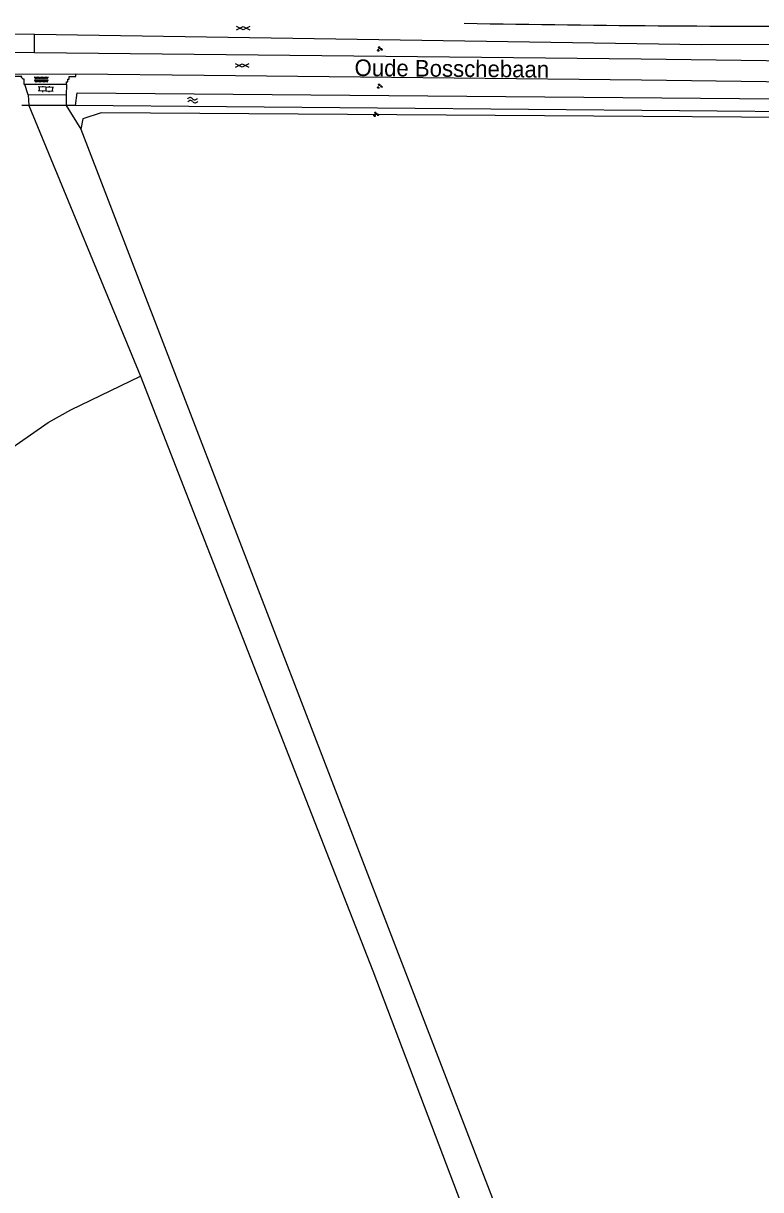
# Model space of a CAD drawing. Extents: x 134297 to 137000, y 403500 to 406000.
# Drawn here: x 136777.7 to 136889, y 405338.4 to 405514.3 of the extents above; entities that cross this region are included whole.
import ezdxf

# ---------------------------------------------------------------- set-up
doc = ezdxf.new("R2010")
doc.units = 0
for name, color, linetype in [('gg-anno-openbare ruimte label', 7, 'Continuous'), ('gg-knt-bronhoudergrens', 7, 'Continuous'), ('gg-knt-onverhard', 7, 'Continuous'), ('gg-knt-verharding', 7, 'Continuous'), ('gg-kntw-bovenkant insteek waterloop', 7, 'Continuous'), ('gt-grn-groengrens', 7, 'Continuous'), ('gt-symb-gesloten verharding', 7, 'Continuous'), ('gt-symb-groenvak', 7, 'Continuous'), ('gt-symb-klinker verharding', 7, 'Continuous'), ('gt-symb-overige verharding', 7, 'Continuous'), ('gt-symb-watersymbool', 7, 'Continuous')]:
    doc.layers.add(name, color=color, linetype=linetype)

# ---------------------------------------------------------------- blocks, each defined once
blk = doc.blocks.new('gt0-WA')
at = {"layer": 'gt-symb-watersymbool'}
for centre, start, end in [((-0.32, 0.02), 28.0725, 151.9275), ((0.43, 0.42), 208.0725, 331.9275), ((-0.32, -0.43), 28.0725, 151.9275), ((0.43, -0.03), 208.0725, 331.9275)]:
    blk.add_arc(centre, 0.425, start, end, dxfattribs=at)
blk = doc.blocks.new('gt0-GESVH1')
at = {"layer": 'gt-symb-gesloten verharding'}
for p, q in [((-0.99, -0.26), (0.01, 0.24)), ((0.01, -0.26), (-0.99, 0.24)), ((0.01, 0.24), (1.01, -0.26)), ((1.01, 0.24), (0.01, -0.26))]:
    blk.add_line(p, q, dxfattribs=at)
blk = doc.blocks.new('gt0-GRVAK')
at = {"layer": 'gt-symb-groenvak'}
for p, q in [((-0.11, 0.19), (-0.23, 0.24)), ((-0.18, 0.15), (0.09, 0.15)), ((-0.09, 0.21), (-0.16, 0.32)), ((-0.05, 0.21), (-0.05, 0.39)), ((0, 0.21), (0.06, 0.32)), ((0.01, 0.19), (0.13, 0.24)), ((0.26, -0.05), (0.2, 0.06)), ((0.3, -0.05), (0.3, 0.13)), ((0.35, -0.05), (0.41, 0.06)), ((-0.24, -0.23), (-0.36, -0.18)), ((-0.32, -0.26), (-0.05, -0.26)), ((-0.23, -0.21), (-0.29, -0.09)), ((-0.18, -0.2), (-0.18, -0.02)), ((-0.14, -0.21), (-0.07, -0.09)), ((-0.12, -0.23), (0, -0.18)), ((0.24, -0.07), (0.12, -0.02)), ((0.17, -0.11), (0.44, -0.11)), ((0.37, -0.07), (0.49, -0.02))]:
    blk.add_line(p, q, dxfattribs=at)
blk = doc.blocks.new('gt0-OVH')
at = {"layer": 'gt-symb-overige verharding'}
for points in [[(-0.97, 0.3), (-0.97, 0.31), (-0.96, 0.32), (-0.97, 0.33), (-0.97, 0.34), (-0.98, 0.35), (-0.99, 0.35), (-1, 0.36), (-1.01, 0.35), (-1.02, 0.35), (-1.03, 0.34), (-1.03, 0.33), (-1.04, 0.32), (-1.03, 0.31), (-1.03, 0.3), (-1.02, 0.29), (-1.01, 0.29), (-1, 0.28), (-0.99, 0.29), (-0.98, 0.29)], [(-0.87, 0.11), (-0.87, 0.12), (-0.86, 0.13), (-0.87, 0.14), (-0.87, 0.15), (-0.88, 0.16), (-0.89, 0.16), (-0.9, 0.16), (-0.91, 0.16), (-0.92, 0.16), (-0.93, 0.15), (-0.93, 0.14), (-0.94, 0.13), (-0.93, 0.12), (-0.93, 0.11), (-0.92, 0.1), (-0.91, 0.09), (-0.9, 0.09), (-0.89, 0.09), (-0.88, 0.1)], [(-0.77, 0.3), (-0.77, 0.31), (-0.76, 0.32), (-0.77, 0.33), (-0.77, 0.34), (-0.78, 0.35), (-0.79, 0.35), (-0.8, 0.36), (-0.81, 0.35), (-0.82, 0.35), (-0.83, 0.34), (-0.83, 0.33), (-0.84, 0.32), (-0.83, 0.31), (-0.83, 0.3), (-0.82, 0.29), (-0.81, 0.29), (-0.8, 0.28), (-0.79, 0.29), (-0.78, 0.29)], [(-0.67, 0.11), (-0.67, 0.12), (-0.66, 0.13), (-0.67, 0.14), (-0.67, 0.15), (-0.68, 0.16), (-0.69, 0.16), (-0.7, 0.16), (-0.71, 0.16), (-0.72, 0.16), (-0.73, 0.15), (-0.73, 0.14), (-0.74, 0.13), (-0.73, 0.12), (-0.73, 0.11), (-0.72, 0.1), (-0.71, 0.09), (-0.7, 0.09), (-0.69, 0.09), (-0.68, 0.1)], [(-0.57, 0.3), (-0.57, 0.31), (-0.56, 0.32), (-0.57, 0.33), (-0.57, 0.34), (-0.58, 0.35), (-0.59, 0.35), (-0.6, 0.36), (-0.61, 0.35), (-0.62, 0.35), (-0.63, 0.34), (-0.63, 0.33), (-0.64, 0.32), (-0.63, 0.31), (-0.63, 0.3), (-0.62, 0.29), (-0.61, 0.29), (-0.6, 0.28), (-0.59, 0.29), (-0.58, 0.29)], [(-0.47, 0.11), (-0.47, 0.12), (-0.46, 0.13), (-0.47, 0.14), (-0.47, 0.15), (-0.48, 0.16), (-0.49, 0.16), (-0.5, 0.16), (-0.51, 0.16), (-0.52, 0.16), (-0.53, 0.15), (-0.53, 0.14), (-0.54, 0.13), (-0.53, 0.12), (-0.53, 0.11), (-0.52, 0.1), (-0.51, 0.09), (-0.5, 0.09), (-0.49, 0.09), (-0.48, 0.1)], [(-0.37, 0.3), (-0.37, 0.31), (-0.36, 0.32), (-0.37, 0.33), (-0.37, 0.34), (-0.38, 0.35), (-0.39, 0.35), (-0.4, 0.36), (-0.41, 0.35), (-0.42, 0.35), (-0.43, 0.34), (-0.43, 0.33), (-0.44, 0.32), (-0.43, 0.31), (-0.43, 0.3), (-0.42, 0.29), (-0.41, 0.29), (-0.4, 0.28), (-0.39, 0.29), (-0.38, 0.29)], [(-0.27, 0.11), (-0.27, 0.12), (-0.26, 0.13), (-0.27, 0.14), (-0.27, 0.15), (-0.28, 0.16), (-0.29, 0.16), (-0.3, 0.16), (-0.31, 0.16), (-0.32, 0.16), (-0.33, 0.15), (-0.33, 0.14), (-0.34, 0.13), (-0.33, 0.12), (-0.33, 0.11), (-0.32, 0.1), (-0.31, 0.09), (-0.3, 0.09), (-0.29, 0.09), (-0.28, 0.1)], [(-0.17, 0.3), (-0.17, 0.31), (-0.16, 0.32), (-0.17, 0.33), (-0.17, 0.34), (-0.18, 0.35), (-0.19, 0.35), (-0.2, 0.36), (-0.21, 0.35), (-0.22, 0.35), (-0.23, 0.34), (-0.23, 0.33), (-0.24, 0.32), (-0.23, 0.31), (-0.23, 0.3), (-0.22, 0.29), (-0.21, 0.29), (-0.2, 0.28), (-0.19, 0.29), (-0.18, 0.29)], [(-0.07, 0.11), (-0.07, 0.12), (-0.06, 0.13), (-0.07, 0.14), (-0.07, 0.15), (-0.08, 0.16), (-0.09, 0.16), (-0.1, 0.16), (-0.11, 0.16), (-0.12, 0.16), (-0.13, 0.15), (-0.13, 0.14), (-0.14, 0.13), (-0.13, 0.12), (-0.13, 0.11), (-0.12, 0.1), (-0.11, 0.09), (-0.1, 0.09), (-0.09, 0.09), (-0.08, 0.1)], [(0.03, 0.3), (0.03, 0.31), (0.04, 0.32), (0.03, 0.33), (0.03, 0.34), (0.02, 0.35), (0.01, 0.35), (0, 0.36), (-0.01, 0.35), (-0.02, 0.35), (-0.03, 0.34), (-0.03, 0.33), (-0.04, 0.32), (-0.03, 0.31), (-0.03, 0.3), (-0.02, 0.29), (-0.01, 0.29), (0, 0.28), (0.01, 0.29), (0.02, 0.29)], [(0.13, 0.11), (0.13, 0.12), (0.14, 0.13), (0.13, 0.14), (0.13, 0.15), (0.12, 0.16), (0.11, 0.16), (0.1, 0.16), (0.09, 0.16), (0.08, 0.16), (0.07, 0.15), (0.07, 0.14), (0.06, 0.13), (0.07, 0.12), (0.07, 0.11), (0.08, 0.1), (0.09, 0.09), (0.1, 0.09), (0.11, 0.09), (0.12, 0.1)], [(0.23, 0.3), (0.23, 0.31), (0.24, 0.32), (0.23, 0.33), (0.23, 0.34), (0.22, 0.35), (0.21, 0.35), (0.2, 0.36), (0.19, 0.35), (0.18, 0.35), (0.17, 0.34), (0.17, 0.33), (0.16, 0.32), (0.17, 0.31), (0.17, 0.3), (0.18, 0.29), (0.19, 0.29), (0.2, 0.28), (0.21, 0.29), (0.22, 0.29)], [(0.33, 0.11), (0.33, 0.12), (0.34, 0.13), (0.33, 0.14), (0.33, 0.15), (0.32, 0.16), (0.31, 0.16), (0.3, 0.16), (0.29, 0.16), (0.28, 0.16), (0.27, 0.15), (0.27, 0.14), (0.26, 0.13), (0.27, 0.12), (0.27, 0.11), (0.28, 0.1), (0.29, 0.09), (0.3, 0.09), (0.31, 0.09), (0.32, 0.1)], [(0.43, 0.3), (0.43, 0.31), (0.44, 0.32), (0.43, 0.33), (0.43, 0.34), (0.42, 0.35), (0.41, 0.35), (0.4, 0.36), (0.39, 0.35), (0.38, 0.35), (0.37, 0.34), (0.37, 0.33), (0.36, 0.32), (0.37, 0.31), (0.37, 0.3), (0.38, 0.29), (0.39, 0.29), (0.4, 0.28), (0.41, 0.29), (0.42, 0.29)], [(0.53, 0.11), (0.53, 0.12), (0.54, 0.13), (0.53, 0.14), (0.53, 0.15), (0.52, 0.16), (0.51, 0.16), (0.5, 0.16), (0.49, 0.16), (0.48, 0.16), (0.47, 0.15), (0.47, 0.14), (0.46, 0.13), (0.47, 0.12), (0.47, 0.11), (0.48, 0.1), (0.49, 0.09), (0.5, 0.09), (0.51, 0.09), (0.52, 0.1)], [(0.63, 0.3), (0.63, 0.31), (0.64, 0.32), (0.63, 0.33), (0.63, 0.34), (0.62, 0.35), (0.61, 0.35), (0.6, 0.36), (0.59, 0.35), (0.58, 0.35), (0.57, 0.34), (0.57, 0.33), (0.56, 0.32), (0.57, 0.31), (0.57, 0.3), (0.58, 0.29), (0.59, 0.29), (0.6, 0.28), (0.61, 0.29), (0.62, 0.29)], [(0.73, 0.11), (0.73, 0.12), (0.74, 0.13), (0.73, 0.14), (0.73, 0.15), (0.72, 0.16), (0.71, 0.16), (0.7, 0.16), (0.69, 0.16), (0.68, 0.16), (0.67, 0.15), (0.67, 0.14), (0.66, 0.13), (0.67, 0.12), (0.67, 0.11), (0.68, 0.1), (0.69, 0.09), (0.7, 0.09), (0.71, 0.09), (0.72, 0.1)], [(0.83, 0.3), (0.83, 0.31), (0.84, 0.32), (0.83, 0.33), (0.83, 0.34), (0.82, 0.35), (0.81, 0.35), (0.8, 0.36), (0.79, 0.35), (0.78, 0.35), (0.77, 0.34), (0.77, 0.33), (0.76, 0.32), (0.77, 0.31), (0.77, 0.3), (0.78, 0.29), (0.79, 0.29), (0.8, 0.28), (0.81, 0.29), (0.82, 0.29)], [(0.93, 0.11), (0.93, 0.12), (0.94, 0.13), (0.93, 0.14), (0.93, 0.15), (0.92, 0.16), (0.91, 0.16), (0.9, 0.16), (0.89, 0.16), (0.88, 0.16), (0.87, 0.15), (0.87, 0.14), (0.86, 0.13), (0.87, 0.12), (0.87, 0.11), (0.88, 0.1), (0.89, 0.09), (0.9, 0.09), (0.91, 0.09), (0.92, 0.1)], [(1.03, 0.3), (1.03, 0.31), (1.04, 0.32), (1.03, 0.33), (1.03, 0.34), (1.02, 0.35), (1.01, 0.35), (1, 0.36), (0.99, 0.35), (0.98, 0.35), (0.97, 0.34), (0.97, 0.33), (0.96, 0.32), (0.97, 0.31), (0.97, 0.3), (0.98, 0.29), (0.99, 0.29), (1, 0.28), (1.01, 0.29), (1.02, 0.29)], [(-0.97, -0.14), (-0.97, -0.13), (-0.96, -0.12), (-0.97, -0.11), (-0.97, -0.1), (-0.98, -0.09), (-0.99, -0.09), (-1, -0.08), (-1.01, -0.09), (-1.02, -0.09), (-1.03, -0.1), (-1.03, -0.11), (-1.04, -0.12), (-1.03, -0.13), (-1.03, -0.14), (-1.02, -0.15), (-1.01, -0.15), (-1, -0.16), (-0.99, -0.15), (-0.98, -0.15)], [(-0.87, -0.33), (-0.87, -0.32), (-0.86, -0.31), (-0.87, -0.3), (-0.87, -0.29), (-0.88, -0.28), (-0.89, -0.28), (-0.9, -0.28), (-0.91, -0.28), (-0.92, -0.28), (-0.93, -0.29), (-0.93, -0.3), (-0.94, -0.31), (-0.93, -0.32), (-0.93, -0.33), (-0.92, -0.34), (-0.91, -0.35), (-0.9, -0.35), (-0.89, -0.35), (-0.88, -0.34)], [(-0.77, -0.14), (-0.77, -0.13), (-0.76, -0.12), (-0.77, -0.11), (-0.77, -0.1), (-0.78, -0.09), (-0.79, -0.09), (-0.8, -0.08), (-0.81, -0.09), (-0.82, -0.09), (-0.83, -0.1), (-0.83, -0.11), (-0.84, -0.12), (-0.83, -0.13), (-0.83, -0.14), (-0.82, -0.15), (-0.81, -0.15), (-0.8, -0.16), (-0.79, -0.15), (-0.78, -0.15)], [(-0.67, -0.33), (-0.67, -0.32), (-0.66, -0.31), (-0.67, -0.3), (-0.67, -0.29), (-0.68, -0.28), (-0.69, -0.28), (-0.7, -0.28), (-0.71, -0.28), (-0.72, -0.28), (-0.73, -0.29), (-0.73, -0.3), (-0.74, -0.31), (-0.73, -0.32), (-0.73, -0.33), (-0.72, -0.34), (-0.71, -0.35), (-0.7, -0.35), (-0.69, -0.35), (-0.68, -0.34)], [(-0.57, -0.14), (-0.57, -0.13), (-0.56, -0.12), (-0.57, -0.11), (-0.57, -0.1), (-0.58, -0.09), (-0.59, -0.09), (-0.6, -0.08), (-0.61, -0.09), (-0.62, -0.09), (-0.63, -0.1), (-0.63, -0.11), (-0.64, -0.12), (-0.63, -0.13), (-0.63, -0.14), (-0.62, -0.15), (-0.61, -0.15), (-0.6, -0.16), (-0.59, -0.15), (-0.58, -0.15)], [(-0.47, -0.33), (-0.47, -0.32), (-0.46, -0.31), (-0.47, -0.3), (-0.47, -0.29), (-0.48, -0.28), (-0.49, -0.28), (-0.5, -0.28), (-0.51, -0.28), (-0.52, -0.28), (-0.53, -0.29), (-0.53, -0.3), (-0.54, -0.31), (-0.53, -0.32), (-0.53, -0.33), (-0.52, -0.34), (-0.51, -0.35), (-0.5, -0.35), (-0.49, -0.35), (-0.48, -0.34)], [(-0.37, -0.14), (-0.37, -0.13), (-0.36, -0.12), (-0.37, -0.11), (-0.37, -0.1), (-0.38, -0.09), (-0.39, -0.09), (-0.4, -0.08), (-0.41, -0.09), (-0.42, -0.09), (-0.43, -0.1), (-0.43, -0.11), (-0.44, -0.12), (-0.43, -0.13), (-0.43, -0.14), (-0.42, -0.15), (-0.41, -0.15), (-0.4, -0.16), (-0.39, -0.15), (-0.38, -0.15)], [(-0.27, -0.33), (-0.27, -0.32), (-0.26, -0.31), (-0.27, -0.3), (-0.27, -0.29), (-0.28, -0.28), (-0.29, -0.28), (-0.3, -0.28), (-0.31, -0.28), (-0.32, -0.28), (-0.33, -0.29), (-0.33, -0.3), (-0.34, -0.31), (-0.33, -0.32), (-0.33, -0.33), (-0.32, -0.34), (-0.31, -0.35), (-0.3, -0.35), (-0.29, -0.35), (-0.28, -0.34)], [(-0.17, -0.14), (-0.17, -0.13), (-0.16, -0.12), (-0.17, -0.11), (-0.17, -0.1), (-0.18, -0.09), (-0.19, -0.09), (-0.2, -0.08), (-0.21, -0.09), (-0.22, -0.09), (-0.23, -0.1), (-0.23, -0.11), (-0.24, -0.12), (-0.23, -0.13), (-0.23, -0.14), (-0.22, -0.15), (-0.21, -0.15), (-0.2, -0.16), (-0.19, -0.15), (-0.18, -0.15)], [(-0.07, -0.33), (-0.07, -0.32), (-0.06, -0.31), (-0.07, -0.3), (-0.07, -0.29), (-0.08, -0.28), (-0.09, -0.28), (-0.1, -0.28), (-0.11, -0.28), (-0.12, -0.28), (-0.13, -0.29), (-0.13, -0.3), (-0.14, -0.31), (-0.13, -0.32), (-0.13, -0.33), (-0.12, -0.34), (-0.11, -0.35), (-0.1, -0.35), (-0.09, -0.35), (-0.08, -0.34)], [(0.03, -0.14), (0.03, -0.13), (0.04, -0.12), (0.03, -0.11), (0.03, -0.1), (0.02, -0.09), (0.01, -0.09), (0, -0.08), (-0.01, -0.09), (-0.02, -0.09), (-0.03, -0.1), (-0.03, -0.11), (-0.04, -0.12), (-0.03, -0.13), (-0.03, -0.14), (-0.02, -0.15), (-0.01, -0.15), (0, -0.16), (0.01, -0.15), (0.02, -0.15)], [(0.13, -0.33), (0.13, -0.32), (0.14, -0.31), (0.13, -0.3), (0.13, -0.29), (0.12, -0.28), (0.11, -0.28), (0.1, -0.28), (0.09, -0.28), (0.08, -0.28), (0.07, -0.29), (0.07, -0.3), (0.06, -0.31), (0.07, -0.32), (0.07, -0.33), (0.08, -0.34), (0.09, -0.35), (0.1, -0.35), (0.11, -0.35), (0.12, -0.34)], [(0.23, -0.14), (0.23, -0.13), (0.24, -0.12), (0.23, -0.11), (0.23, -0.1), (0.22, -0.09), (0.21, -0.09), (0.2, -0.08), (0.19, -0.09), (0.18, -0.09), (0.17, -0.1), (0.17, -0.11), (0.16, -0.12), (0.17, -0.13), (0.17, -0.14), (0.18, -0.15), (0.19, -0.15), (0.2, -0.16), (0.21, -0.15), (0.22, -0.15)], [(0.33, -0.33), (0.33, -0.32), (0.34, -0.31), (0.33, -0.3), (0.33, -0.29), (0.32, -0.28), (0.31, -0.28), (0.3, -0.28), (0.29, -0.28), (0.28, -0.28), (0.27, -0.29), (0.27, -0.3), (0.26, -0.31), (0.27, -0.32), (0.27, -0.33), (0.28, -0.34), (0.29, -0.35), (0.3, -0.35), (0.31, -0.35), (0.32, -0.34)], [(0.43, -0.14), (0.43, -0.13), (0.44, -0.12), (0.43, -0.11), (0.43, -0.1), (0.42, -0.09), (0.41, -0.09), (0.4, -0.08), (0.39, -0.09), (0.38, -0.09), (0.37, -0.1), (0.37, -0.11), (0.36, -0.12), (0.37, -0.13), (0.37, -0.14), (0.38, -0.15), (0.39, -0.15), (0.4, -0.16), (0.41, -0.15), (0.42, -0.15)], [(0.53, -0.33), (0.53, -0.32), (0.54, -0.31), (0.53, -0.3), (0.53, -0.29), (0.52, -0.28), (0.51, -0.28), (0.5, -0.28), (0.49, -0.28), (0.48, -0.28), (0.47, -0.29), (0.47, -0.3), (0.46, -0.31), (0.47, -0.32), (0.47, -0.33), (0.48, -0.34), (0.49, -0.35), (0.5, -0.35), (0.51, -0.35), (0.52, -0.34)], [(0.63, -0.14), (0.63, -0.13), (0.64, -0.12), (0.63, -0.11), (0.63, -0.1), (0.62, -0.09), (0.61, -0.09), (0.6, -0.08), (0.59, -0.09), (0.58, -0.09), (0.57, -0.1), (0.57, -0.11), (0.56, -0.12), (0.57, -0.13), (0.57, -0.14), (0.58, -0.15), (0.59, -0.15), (0.6, -0.16), (0.61, -0.15), (0.62, -0.15)], [(0.73, -0.33), (0.73, -0.32), (0.74, -0.31), (0.73, -0.3), (0.73, -0.29), (0.72, -0.28), (0.71, -0.28), (0.7, -0.28), (0.69, -0.28), (0.68, -0.28), (0.67, -0.29), (0.67, -0.3), (0.66, -0.31), (0.67, -0.32), (0.67, -0.33), (0.68, -0.34), (0.69, -0.35), (0.7, -0.35), (0.71, -0.35), (0.72, -0.34)], [(0.83, -0.14), (0.83, -0.13), (0.84, -0.12), (0.83, -0.11), (0.83, -0.1), (0.82, -0.09), (0.81, -0.09), (0.8, -0.08), (0.79, -0.09), (0.78, -0.09), (0.77, -0.1), (0.77, -0.11), (0.76, -0.12), (0.77, -0.13), (0.77, -0.14), (0.78, -0.15), (0.79, -0.15), (0.8, -0.16), (0.81, -0.15), (0.82, -0.15)], [(0.93, -0.33), (0.93, -0.32), (0.94, -0.31), (0.93, -0.3), (0.93, -0.29), (0.92, -0.28), (0.91, -0.28), (0.9, -0.28), (0.89, -0.28), (0.88, -0.28), (0.87, -0.29), (0.87, -0.3), (0.86, -0.31), (0.87, -0.32), (0.87, -0.33), (0.88, -0.34), (0.89, -0.35), (0.9, -0.35), (0.91, -0.35), (0.92, -0.34)], [(1.03, -0.14), (1.03, -0.13), (1.04, -0.12), (1.03, -0.11), (1.03, -0.1), (1.02, -0.09), (1.01, -0.09), (1, -0.08), (0.99, -0.09), (0.98, -0.09), (0.97, -0.1), (0.97, -0.11), (0.96, -0.12), (0.97, -0.13), (0.97, -0.14), (0.98, -0.15), (0.99, -0.15), (1, -0.16), (1.01, -0.15), (1.02, -0.15)]]:
    blk.add_lwpolyline(points, close=True, dxfattribs=at)
blk = doc.blocks.new('gt0-KL1')
at = {"layer": 'gt-symb-klinker verharding'}
for p, q in [((-1.15, 0.3), (1.15, 0.3)), ((-1, -0.3), (-1, 0.3)), ((-0.5, 0.3), (-0.5, 0.45)), ((0, -0.3), (0, 0.3)), ((0.5, 0.3), (0.5, 0.45)), ((1, -0.3), (1, 0.3)), ((-1.15, -0.3), (1.15, -0.3)), ((-0.5, -0.45), (-0.5, -0.3)), ((0.5, -0.45), (0.5, -0.3))]:
    blk.add_line(p, q, dxfattribs=at)

msp = doc.modelspace()

# ---------------------------------------------------------------- linework, layer by layer
at = {"layer": 'gg-knt-bronhoudergrens'}
for points in [[(136982.16, 405491.19), (136975.99, 405496.55), (136975.19, 405497.96), (136971.93, 405499.01), (136967.84, 405499.55), (136789.44, 405500.77), (136786.7, 405499.86), (136786.39, 405498.33)], [(136730.21, 405423.84), (136751.64, 405432.16), (136755.68, 405433.76), (136761.61, 405440.18), (136772.84, 405447.35), (136776.6, 405450.71), (136781.44, 405454.06), (136784.85, 405455.99), (136795.36, 405461.05)], [(136795.36, 405461.05), (136803.74, 405439.64), (136830.46, 405371.38), (136853.7, 405310.14), (136858.32, 405298.22), (136861.21, 405294.59)]]:
    msp.add_lwpolyline(points, dxfattribs=at)
at = {"layer": 'gg-knt-onverhard'}
for p, q in [((136778.54, 405501.88), (136795.36, 405461.05)), ((136784.18, 405501.89), (136786.39, 405498.33)), ((136786.39, 405498.33), (136856.44, 405316.4))]:
    msp.add_line(p, q, dxfattribs=at)
at = {"layer": 'gg-knt-verharding'}
for p, q in [((136734.68, 405510.35), (136779.37, 405509.87)), ((136776, 405506.64), (136785.63, 405506.59)), ((136778.41, 405503.5), (136777.92, 405505.06)), ((136784.22, 405505.04), (136777.92, 405505.06)), ((136784.22, 405505.04), (136784.18, 405503.46)), ((136784.18, 405503.46), (136778.41, 405503.5))]:
    msp.add_line(p, q, dxfattribs=at)
for points in [[(136734.69, 405513.46), (136738.63, 405513.42), (136757.83, 405513.01), (136779.4, 405512.67)], [(136779.4, 405512.67), (136880.05, 405511.09), (136927.48, 405511.2)], [(136779.37, 405509.87), (136870.95, 405508.91), (136927.44, 405508.16)], [(136777.92, 405505.06), (136777.8, 405505.06), (136777.83, 405505.86), (136777.66, 405505.86), (136777.43, 405506.09), (136777.46, 405506.24), (136776, 405506.27), (136776, 405506.64)], [(136784.22, 405505.04), (136784.23, 405505.45), (136784.41, 405505.44), (136784.43, 405505.85), (136784.6, 405505.84), (136784.62, 405506.24), (136785.63, 405506.26), (136785.63, 405506.59)], [(136965, 405504.44), (136870.99, 405505.69), (136804.99, 405506.43), (136785.63, 405506.59)]]:
    msp.add_lwpolyline(points, dxfattribs=at)
msp.add_arc((136899.8, 408811.91), 3298.09, 269.03471, 270.1185, dxfattribs=at)
at = {"layer": 'gg-kntw-bovenkant insteek waterloop'}
for points in [[(136785.58, 405501.89), (136785.83, 405503.81), (136968.11, 405502.23)], [(136971.65, 405500), (136969.76, 405500.19), (136967.87, 405500.3), (136785.58, 405501.89)]]:
    msp.add_lwpolyline(points, dxfattribs=at)
at = {"layer": 'gt-grn-groengrens'}
for p, q in [((136779.37, 405509.87), (136779.4, 405512.67)), ((136778.41, 405503.5), (136778.54, 405501.88)), ((136784.18, 405503.46), (136784.18, 405501.89)), ((136778.54, 405501.88), (136777.48, 405501.88)), ((136784.18, 405501.89), (136778.54, 405501.88)), ((136785.58, 405501.89), (136784.18, 405501.89))]:
    msp.add_line(p, q, dxfattribs=at)

# ---------------------------------------------------------------- block references
at = {"layer": 'gt-symb-gesloten verharding'}
for p in [(136810.86, 405513.58), (136810.7, 405507.94)]:
    msp.add_blockref('gt0-GESVH1', p, dxfattribs=at)
at = {"layer": 'gt-symb-groenvak'}
for p in [(136831.46, 405510.4), (136831.46, 405504.79), (136830.9, 405500.56)]:
    msp.add_blockref('gt0-GRVAK', p, dxfattribs=at)
at = {"layer": 'gt-symb-klinker verharding', "rotation": 178.33888795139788}
msp.add_blockref('gt0-KL1', (136781.08, 405504.35), dxfattribs=at)
at = {"layer": 'gt-symb-overige verharding', "rotation": -0.22918189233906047}
msp.add_blockref('gt0-OVH', (136780.42, 405505.8), dxfattribs=at)
at = {"layer": 'gt-symb-watersymbool', "rotation": 7.004259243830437}
msp.add_blockref('gt0-WA', (136803.19, 405502.69), dxfattribs=at)

# ---------------------------------------------------------------- texts
at = {"layer": 'gg-anno-openbare ruimte label'}
msp.add_text('Oude Bosschebaan', height=2.5, rotation=359.5, dxfattribs=at).set_placement((136827.67, 405506.34))

doc.saveas('drawing.dxf')
